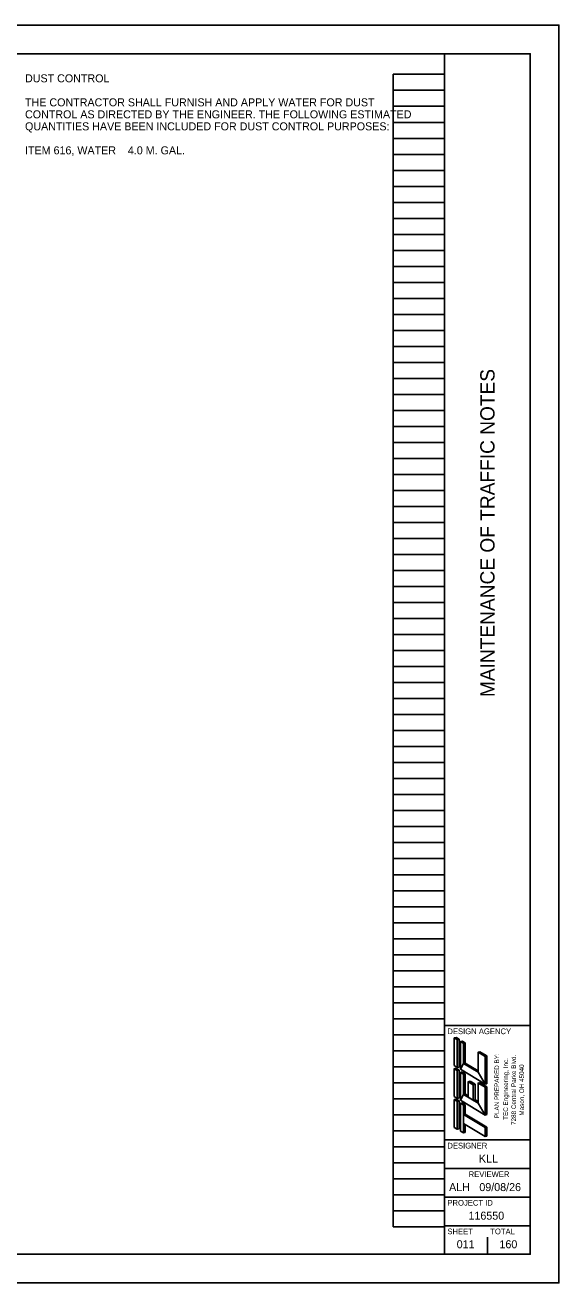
# Model space of a CAD drawing. Extents: x -6.4 to 60.5, y 0 to 37.1.
# Drawn here: x 24.66 to 34, y 0 to 22 of the extents above; entities that cross this region are included whole.
import ezdxf

# ---------------------------------------------------------------- set-up
doc = ezdxf.new("R2010")
doc.units = 0
for name, color, linetype in [('Default', 7, 'Continuous'), ('SH_Border', 7, 'Continuous'), ('SH_Cut_Line', 7, 'Continuous'), ('SH_Data', 7, 'Continuous'), ('SH_Text', 7, 'Continuous')]:
    doc.layers.add(name, color=color, linetype=linetype)

msp = doc.modelspace()

# ---------------------------------------------------------------- linework, layer by layer
at = {"layer": 'SH_Border'}
for p, q in [((32, 0.5), (32, 21.5)), ((32, 4.5), (33.5, 4.5)), ((32, 2.5), (33.5, 2.5)), ((32, 2), (33.5, 2)), ((32, 1.5), (33.5, 1.5)), ((32, 1), (33.5, 1))]:
    msp.add_line(p, q, dxfattribs=at)
msp.add_lwpolyline([(1.5, 21.5), (33.5, 21.5), (33.5, 0.5), (1.5, 0.5)], close=True, dxfattribs=at)
at = {"layer": 'SH_Cut_Line'}
msp.add_lwpolyline([(0, 0), (34, 0), (34, 22), (0, 22)], close=True, dxfattribs=at)
at = {"layer": 'SH_Data'}
for p, q in [((31.1, 0.98), (31.1, 21.14)), ((31.1, 21.14), (32, 21.14)), ((32, 0.98), (32, 21.14)), ((31.1, 20.86), (32, 20.86)), ((31.1, 20.58), (32, 20.58)), ((31.1, 20.3), (32, 20.3)), ((31.1, 20.02), (32, 20.02)), ((31.1, 19.74), (32, 19.74)), ((31.1, 19.46), (32, 19.46)), ((31.1, 19.18), (32, 19.18)), ((31.1, 18.9), (32, 18.9)), ((31.1, 18.62), (32, 18.62)), ((31.1, 18.34), (32, 18.34)), ((31.1, 18.06), (32, 18.06)), ((31.1, 17.78), (32, 17.78)), ((31.1, 17.5), (32, 17.5)), ((31.1, 17.22), (32, 17.22)), ((31.1, 16.94), (32, 16.94)), ((31.1, 16.66), (32, 16.66)), ((31.1, 16.38), (32, 16.38)), ((31.1, 16.1), (32, 16.1)), ((31.1, 15.82), (32, 15.82)), ((31.1, 15.54), (32, 15.54)), ((31.1, 15.26), (32, 15.26)), ((31.1, 14.98), (32, 14.98)), ((31.1, 14.7), (32, 14.7)), ((31.1, 14.42), (32, 14.42)), ((31.1, 14.14), (32, 14.14)), ((31.1, 13.86), (32, 13.86)), ((31.1, 13.58), (32, 13.58)), ((31.1, 13.3), (32, 13.3)), ((31.1, 13.02), (32, 13.02)), ((31.1, 12.74), (32, 12.74)), ((31.1, 12.46), (32, 12.46)), ((31.1, 12.18), (32, 12.18)), ((31.1, 11.9), (32, 11.9)), ((31.1, 11.62), (32, 11.62)), ((31.1, 11.34), (32, 11.34)), ((31.1, 11.06), (32, 11.06)), ((31.1, 10.78), (32, 10.78)), ((31.1, 10.5), (32, 10.5)), ((31.1, 10.22), (32, 10.22)), ((31.1, 9.94), (32, 9.94)), ((31.1, 9.66), (32, 9.66)), ((31.1, 9.38), (32, 9.38)), ((31.1, 9.1), (32, 9.1)), ((31.1, 8.82), (32, 8.82)), ((31.1, 8.54), (32, 8.54)), ((31.1, 8.26), (32, 8.26)), ((31.1, 7.98), (32, 7.98)), ((31.1, 7.7), (32, 7.7)), ((31.1, 7.42), (32, 7.42)), ((31.1, 7.14), (32, 7.14)), ((31.1, 6.86), (32, 6.86)), ((31.1, 6.58), (32, 6.58)), ((31.1, 6.3), (32, 6.3)), ((31.1, 6.02), (32, 6.02)), ((31.1, 5.74), (32, 5.74)), ((31.1, 5.46), (32, 5.46)), ((31.1, 5.18), (32, 5.18)), ((31.1, 4.9), (32, 4.9)), ((31.1, 4.62), (32, 4.62)), ((31.1, 4.34), (32, 4.34)), ((31.1, 4.06), (32, 4.06)), ((31.1, 3.78), (32, 3.78)), ((31.1, 3.5), (32, 3.5)), ((32.75, 3.5), (32.75, 3.5)), ((31.1, 3.22), (32, 3.22)), ((31.1, 2.94), (32, 2.94)), ((31.1, 2.66), (32, 2.66)), ((31.1, 2.38), (32, 2.38)), ((31.1, 2.1), (32, 2.1)), ((31.1, 1.82), (32, 1.82)), ((31.1, 1.54), (32, 1.54)), ((31.1, 1.26), (32, 1.26)), ((31.1, 0.98), (32, 0.98)), ((32.375, 0.675), (32.375, 0.675)), ((32.75, 0.5), (32.75, 0.8))]:
    msp.add_line(p, q, dxfattribs=at)
at = {"layer": 'SH_Text'}
for p, q in [((32.169, 4.285), (32.201, 4.294)), ((32.169, 3.799), (32.169, 4.285)), ((32.223, 4.253), (32.169, 4.285)), ((32.255, 4.261), (32.201, 4.294)), ((32.223, 4.253), (32.255, 4.261)), ((32.223, 3.767), (32.223, 4.253)), ((32.255, 3.775), (32.255, 4.261)), ((32.277, 4.221), (32.309, 4.229)), ((32.331, 4.188), (32.277, 4.221)), ((32.277, 3.735), (32.277, 4.221)), ((32.309, 4.229), (32.363, 4.196)), ((32.331, 4.188), (32.363, 4.196)), ((32.331, 3.837), (32.331, 4.188)), ((32.363, 4.196), (32.363, 3.845)), ((32.587, 4.034), (32.62, 4.042)), ((32.587, 3.683), (32.587, 4.034)), ((32.709, 3.961), (32.587, 4.034)), ((32.62, 4.042), (32.741, 3.97)), ((32.709, 3.961), (32.741, 3.97)), ((32.709, 3.475), (32.709, 3.961)), ((32.741, 3.97), (32.741, 3.484)), ((32.223, 3.767), (32.169, 3.799)), ((32.169, 3.745), (32.201, 3.754)), ((32.169, 3.259), (32.169, 3.745)), ((32.223, 3.713), (32.169, 3.745)), ((32.255, 3.722), (32.201, 3.754)), ((32.223, 3.767), (32.255, 3.775)), ((32.331, 3.837), (32.363, 3.845)), ((32.587, 3.683), (32.331, 3.837)), ((32.363, 3.845), (32.587, 3.711)), ((32.223, 3.713), (32.255, 3.722)), ((32.223, 3.227), (32.223, 3.713)), ((32.255, 3.236), (32.255, 3.722)), ((32.709, 3.475), (32.277, 3.735)), ((32.277, 3.681), (32.309, 3.689)), ((32.277, 3.195), (32.277, 3.681)), ((32.331, 3.648), (32.277, 3.681)), ((32.309, 3.689), (32.363, 3.656)), ((32.331, 3.648), (32.363, 3.656)), ((32.331, 3.297), (32.331, 3.648)), ((32.363, 3.656), (32.363, 3.305)), ((32.415, 3.519), (32.448, 3.527)), ((32.448, 3.527), (32.535, 3.474)), ((32.331, 3.297), (32.363, 3.305)), ((32.363, 3.305), (32.415, 3.274)), ((32.415, 3.519), (32.415, 3.247)), ((32.415, 3.519), (32.503, 3.466)), ((32.503, 3.466), (32.535, 3.474)), ((32.503, 3.466), (32.503, 3.194)), ((32.535, 3.474), (32.535, 3.202)), ((32.587, 3.494), (32.62, 3.502)), ((32.587, 3.143), (32.587, 3.494)), ((32.709, 3.421), (32.587, 3.494)), ((32.62, 3.502), (32.741, 3.43)), ((32.709, 3.475), (32.741, 3.484)), ((32.709, 3.421), (32.741, 3.43)), ((32.709, 2.935), (32.709, 3.421)), ((32.741, 3.43), (32.741, 2.944)), ((32.223, 3.227), (32.169, 3.259)), ((32.169, 3.205), (32.201, 3.215)), ((32.169, 2.719), (32.169, 3.205)), ((32.223, 3.173), (32.169, 3.205)), ((32.255, 3.181), (32.201, 3.215)), ((32.222, 3.173), (32.255, 3.181)), ((32.223, 3.227), (32.255, 3.236)), ((32.223, 2.687), (32.223, 3.173)), ((32.255, 2.695), (32.255, 3.181)), ((32.709, 2.935), (32.277, 3.195)), ((32.277, 3.141), (32.309, 3.151)), ((32.331, 3.108), (32.277, 3.141)), ((32.277, 2.655), (32.277, 3.141)), ((32.309, 3.151), (32.363, 3.116)), ((32.415, 3.247), (32.331, 3.297)), ((32.331, 3.108), (32.363, 3.116)), ((32.331, 2.944), (32.331, 3.108)), ((32.363, 3.116), (32.363, 2.952)), ((32.503, 3.194), (32.535, 3.202)), ((32.587, 3.143), (32.503, 3.194)), ((32.535, 3.202), (32.587, 3.171)), ((32.331, 2.944), (32.363, 2.952)), ((32.331, 2.944), (32.709, 2.717)), ((32.363, 2.952), (32.741, 2.725)), ((32.709, 2.935), (32.741, 2.944)), ((32.223, 2.687), (32.169, 2.719)), ((32.223, 2.687), (32.255, 2.695)), ((32.331, 2.622), (32.277, 2.655)), ((32.331, 2.787), (32.709, 2.56)), ((32.331, 2.622), (32.331, 2.787)), ((32.363, 2.63), (32.363, 2.767)), ((32.709, 2.717), (32.741, 2.725)), ((32.709, 2.56), (32.709, 2.717)), ((32.741, 2.725), (32.741, 2.568)), ((32.331, 2.622), (32.363, 2.63)), ((32.709, 2.56), (32.741, 2.568))]:
    msp.add_line(p, q, dxfattribs=at)
for points in [[(32.169, 3.799), (32.223, 3.767), (32.223, 4.253), (32.169, 4.285)], [(32.277, 3.735), (32.331, 3.837), (32.331, 4.188), (32.277, 4.221)], [(32.709, 3.475), (32.587, 3.683), (32.587, 4.034), (32.709, 3.961)], [(32.169, 3.259), (32.223, 3.227), (32.223, 3.713), (32.169, 3.745)], [(32.277, 3.735), (32.331, 3.837), (32.587, 3.683), (32.709, 3.475)], [(32.277, 3.195), (32.331, 3.297), (32.331, 3.648), (32.277, 3.681)], [(32.415, 3.247), (32.415, 3.519), (32.503, 3.466), (32.503, 3.194)], [(32.709, 2.935), (32.587, 3.143), (32.587, 3.494), (32.709, 3.421)], [(32.169, 2.719), (32.223, 2.687), (32.223, 3.173), (32.169, 3.205)], [(32.277, 3.195), (32.331, 3.297), (32.587, 3.143), (32.709, 2.935)], [(32.277, 2.655), (32.331, 2.622), (32.331, 3.108), (32.277, 3.141)], [(32.331, 2.787), (32.331, 2.944), (32.709, 2.717), (32.709, 2.56)]]:
    msp.add_lwpolyline(points, close=True, dxfattribs=at)

# ---------------------------------------------------------------- texts
at = {"layer": 'Default'}
for s, p in [('PLAN PREPARED BY:', (32.954, 2.88)), ('TEC Engineering, Inc.', (33.11, 2.851)), ('7288 Central Parke Blvd.', (33.25, 2.762)), ('Mason, OH 45040', (33.39, 2.925))]:
    msp.add_text(s, height=0.08, rotation=90, dxfattribs=at).set_placement(p)
at = {"layer": 'SH_Data'}
msp.add_text('MAINTENANCE OF TRAFFIC NOTES', height=0.25, rotation=90, dxfattribs=at).set_placement((32.875, 10.247))
for s, height, p in [('DESIGN AGENCY', 0.1, (32.05, 4.35)), ('DESIGNER', 0.1, (32.05, 2.35)), ('KLL', 0.14, (32.601, 2.105)), ('REVIEWER', 0.1, (32.422, 1.85)), ('ALH', 0.14, (32.08, 1.605)), ('09/08/26', 0.14, (32.609, 1.605)), ('PROJECT ID', 0.1, (32.05, 1.35)), ('116550', 0.14, (32.419, 1.105)), ('SHEET', 0.1, (32.05, 0.85)), ('TOTAL', 0.1, (32.8, 0.85)), ('011', 0.14, (32.213, 0.605)), ('160', 0.14, (32.961, 0.605))]:
    msp.add_text(s, height=height, dxfattribs=at).set_placement(p)
at = {"layer": 'SH_Text'}
for s, p in [('DUST CONTROL', (24.66, 21)), ('THE CONTRACTOR SHALL FURNISH AND APPLY WATER FOR DUST ', (24.66, 20.58)), ('CONTROL AS DIRECTED BY THE ENGINEER. THE FOLLOWING ESTIMATED ', (24.66, 20.37)), ('QUANTITIES HAVE BEEN INCLUDED FOR DUST CONTROL PURPOSES:', (24.66, 20.16)), ('ITEM 616, WATER    4.0 M. GAL.', (24.66, 19.74))]:
    msp.add_text(s, height=0.14, dxfattribs=at).set_placement(p)

doc.saveas('drawing.dxf')
